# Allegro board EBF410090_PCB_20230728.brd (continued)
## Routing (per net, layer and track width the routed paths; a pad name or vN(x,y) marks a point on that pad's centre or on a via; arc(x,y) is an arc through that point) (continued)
I2C1_SCL: length 194.7
  TOP w0.156: v1(106.5,48.39) 103.81,51.08 88.04,51.08 87.3,50.34 87.3,28.75 86.84,28.3 84.18,28.3 v1(83.57,27.68) ; R164.2 127.48,68.12 J18.9 131.17,68.12 131.51,67.79 131.51,66.33 131.82,66.02 134.61,66.02 135.03,66.43 135.03,67.76 v1(134.55,68.24) ; v1(39.88,18.92) 40.36,19.4 40.36,31.72 41.26,32.62 J30.150
  ART03 w0.142: v1(39.88,18.92) 40.44,19.48 72.06,19.48 73.28,20.7 73.28,24.26 76.71,27.68 v1(83.57,27.68) ; v1(134.55,68.24) 135.7,67.08 135.7,54.13 134.53,52.96 122.99,52.96 120.6,50.57 115.44,50.57 113.26,48.39 v1(106.5,48.39)
  BOTTOM w0.156: J20.6 133.09,70.16 134.55,68.7 v1(134.55,68.24)
I2C1_SDA: length 189.1
  TOP w0.156: v1(134.55,67.24) 134.55,66.93 134.14,66.52 132.29,66.52 131.98,66.83 131.98,68.02 131.38,68.62 J18.10 127.38,68.62 R168.2 ; v1(40.89,18.92) 40.89,30.02 41.76,30.89 J30.148 ; v1(105.5,48.39) 103.37,50.52 88.37,50.52 87.78,49.94 87.78,28.35 87.12,27.68 v1(84.71,27.68)
  ART03 w0.142: v1(105.5,48.39) 106.01,48.89 113.09,48.89 115.73,51.54 120.75,51.54 122.63,53.42 134.11,53.42 135.28,54.58 135.28,66.51 v1(134.55,67.24) ; v1(84.71,27.68) 84.2,27.18 76.96,27.18 73.79,24 73.79,20.51 72.22,18.95 40.92,18.95 v1(40.89,18.92)
  BOTTOM w0.156: J20.5 132.83,69.65 134.04,68.45 134.04,67.75 v1(134.55,67.24)
I2C2_SCL_M1: length 62.8
  TOP w0.156: v1(76.58,17.02) R222.2 ; J30.55 67.01,60.78
  TOP w0.305: 67.01,60.78 v1(67.01,60.78)
  BOTTOM w0.156: v1(76.58,17.02) 77.07,16.53 81.3,16.53 82.68,17.91 82.68,47.75 81.38,49.05 81.38,52.32 80.57,53.14 73.18,53.14 67.5,58.82 67.5,60.3 v1(67.01,60.78)
I2C2_SDA_M1: length 56.9
  TOP w0.156: J30.61 65.51,60.28 v1(66.01,59.78) ; v1(81.06,17.02) R233.2
  BOTTOM w0.156: v1(66.01,59.78) 66.01,59.64 73.03,52.63 79.25,52.63 80.9,50.98 80.9,48.77 82.17,47.5 82.17,18.12 v1(81.06,17.02)
I2C3_SCL_M0: length 47.5
  TOP w0.156: J30.46 69.26,46.43 69.85,45.85 70.36,45.85 70.61,45.59 70.61,40.18 73.2,37.59 73.2,32.6 74.05,31.76 74.05,29.2 76.33,26.92 79.5,26.92 v1(79.88,26.54) ; R237.2 v1(86.49,26.03)
  ART03 w0.142: v1(79.88,26.54) 80.39,26.03 v1(86.49,26.03)
I2C3_SDA_M0: length 48.1
  TOP w0.156: v1(80.9,26.54) 80.01,27.43 76.58,27.43 74.52,29.49 74.52,31.93 73.66,32.79 73.66,37.84 71.12,40.38 71.12,48.13 69.76,49.49 J30.44 ; R238.2 v1(87.76,26.54)
  ART03 w0.142: v1(80.9,26.54) v1(87.76,26.54)
I2C4_SCL_M0: length 91.6
  TOP w0.156: J30.57 66.51,60.28 v1(67.01,59.78) ; v1(54.05,41.67) 53.47,41.08 53.47,35.18 55.5,33.15 55.5,28.07 56.26,27.3 68.58,27.3 70.1,25.78 72.26,25.78 73.28,24.76 73.28,11.3 71.86,9.89 66.79,9.89 J23.4
  BOTTOM w0.156: v1(67.01,59.78) 66.5,60.3 66.5,61.29 65.91,61.87 57.86,61.87 57.02,61.04 57.02,59.43 56.13,58.55 56.13,56.77 52.83,53.47 52.83,42.89 v1(54.05,41.67)
I2C4_SDA_M0: length 83.4
  TOP w0.156: J30.59 66.01,60.78 ; v1(54.05,42.67) 52.96,41.57 52.96,34.92 54.99,32.89 54.99,27.3 55.63,26.67 68.33,26.67 69.85,25.14 72.14,25.14 72.77,24.51 72.77,12.76 71.57,11.56 68.9,11.56 J23.5
  TOP w0.305: 66.01,60.78 v1(66.01,60.78)
  BOTTOM w0.156: v1(54.05,42.67) 53.34,43.38 53.34,53.08 56.77,56.51 56.77,58.04 58.03,59.3 58.03,60.98 58.36,61.31 65.48,61.31 v1(66.01,60.78)
I2C5_SCL_M0: length 102.8
  TOP w0.156: R166.2 127.48,46.03 J19.9 133.28,46.03 133.63,46.38 v1(133.63,52.39) ; v1(71.93,41.76) 71.63,42.06 71.63,48.26 70.26,49.62 J30.42
  ART03 w0.142: v1(71.93,41.76) 71.93,42.24 72.54,42.85 79.32,42.85 80.49,44.02 88.21,44.02 90.02,45.82 99.21,45.82 100,45.03 113.97,45.03 116.4,47.46 v1(117.83,47.46)
  ART04 w0.142: v1(117.83,47.46) 117.83,46.2 119.13,44.91 127.51,44.91 127.73,45.13 129.28,45.13 129.69,45.54 129.69,51.65 129.91,51.87 133.11,51.87 v1(133.63,52.39)
  BOTTOM w0.156: v1(133.63,52.39) 132.63,53.39 J21.6
I2C5_SDA_M0: length 96.1
  TOP w0.156: R170.2 127.38,46.53 J19.10 132.38,46.53 132.63,46.78 v1(132.63,52.39) ; v1(72.69,42.11) 72.13,42.68 72.13,48.39 70.76,49.76 J30.40
  ART03 w0.142: v1(72.69,42.11) 73.08,41.73 80.29,41.73 81.58,43.03 88.49,43.03 89.41,43.94 114.07,43.94 116.59,46.46 v1(118.83,46.46)
  ART04 w0.142: v1(118.83,46.46) 119.34,45.95 121.49,45.95 121.89,45.54 127.23,45.54 128.4,46.71 128.4,52.95 128.68,53.24 131.78,53.24 v1(132.63,52.39)
  BOTTOM w0.156: J21.5 132.13,52.89 v1(132.63,52.39)
LCD0_BL_PWM: length 204.7
  TOP w0.156: v1(83.69,12.19) 83.69,15.37 83.44,15.62 83.44,26.61 83.75,26.92 87.38,26.92 88.27,27.81 88.27,49.67 88.58,49.99 102.9,49.99 v1(104.5,48.39) ; J30.163 38.01,60.28 v1(38.51,59.78) ; v1(46.43,13.66) 46.1,14 46.1,17.25 43.41,19.94 43.41,28.6 44.2,29.39 44.2,31.57 44.76,32.14 v1(44.76,51.58) ; v1(132.55,67.24) 133.04,67.74 133.04,69.52 132.44,70.12 J18.13
  ART03 w0.142: v1(44.76,51.58) 44.22,52.12 44.22,57.68 43.38,58.52 38.73,58.52 38.51,58.74 v1(38.51,59.78) ; v1(83.69,12.19) 72.39,12.19 70.9,13.68 50.09,13.68 50.07,13.66 v1(46.43,13.66) ; v1(132.55,67.24) 134.82,64.96 134.82,54.86 133.81,53.85 122.38,53.85 120.55,52.02 115.53,52.02 112.79,49.27 105.39,49.27 v1(104.5,48.39)
LCD1_BL_PWM: length 118.3
  TOP w0.156: J30.161 38.51,60.78 v1(38.51,60.78) ; v1(124.35,49.02) 124.91,48.46 128.3,48.46 128.73,48.03 J19.13
  ART03 w0.142: v1(38.51,60.78) 38.02,60.3 38.02,58.27 38.31,57.99 43,57.99 43.71,57.28 43.71,45.06 48.64,40.13 57.68,40.13 59.92,42.37 66.55,42.37 67.69,41.22 80.82,41.22 81.53,41.93 88.8,41.93 89.92,43.05 120.65,43.05 122.15,44.55 122.15,48.74 122.43,49.02 v1(124.35,49.02)
MDIN0_PHY: length 67
  ART04 w0.113: J14.3 78.95,73.23 79.11,73.39 79.9,73.39 80.11,73.18 80.11,65.42 78,63.31 78,60.19 77.05,59.23 56.82,59.23 56.16,58.57 56.16,50.76 55.11,49.71 55.11,40.97 55.45,40.63 57.27,40.63 57.61,40.97 57.61,42.59 57.2,43 56.62,43 v1(56.31,43.3)
  BOTTOM w0.124: v1(56.31,43.3) 56.61,43 59.68,43 59.72,43.05 U16.2
MDIN1_PHY: length 76.6
  ART04 w0.113: J14.7 73.87,75.75 74.07,75.94 76.13,75.94 76.32,75.76 76.32,74.06 77.43,72.94 77.43,69.93 76.8,69.29 76.8,65 74.27,62.47 56.63,62.47 55.75,61.59 54.74,61.59 53.32,60.17 53.32,40.28 53.86,39.74 58.18,39.74 58.91,40.47 58.91,43.87 58.58,44.21 58.13,44.21 v1(57.82,44.51)
  BOTTOM w0.124: v1(57.82,44.51) 58.12,44.21 59.69,44.21 59.72,44.25 U16.5
MDIN2_PHY: length 76.1
  ART04 w0.113: J14.6 75.04,74.64 75.04,65.38 73.21,63.55 56.32,63.55 55.29,62.52 54.1,62.52 52.6,61.03 52.6,39.78 53.38,39 59.12,39 60.22,40.11 60.22,43.92 58.65,45.48 56.52,45.48 v1(56.31,45.69)
  BOTTOM w0.124: v1(56.31,45.69) 56.46,45.54 58.04,45.54 58.57,45.01 59.69,45.01 59.72,45.05 U16.7
MDIN3_PHY: length 79.5
  ART04 w0.113: J14.9 71.33,73.46 71.45,73.58 71.94,73.58 72.46,73.06 72.46,70.39 71.87,69.8 71.87,65.76 70.4,64.3 55.66,64.3 54.7,63.33 53.72,63.33 51.88,61.5 51.88,45.62 51.31,45.05 51.31,39.34 52.45,38.2 59.6,38.2 60.71,39.31 62.04,39.31 62.56,39.83 62.56,41.07 61.34,42.29 61.34,44.63 59.08,46.89 57.99,46.89 v1(57.82,47.06)
  BOTTOM w0.124: v1(57.82,47.06) 58.12,46.76 58.9,46.76 59.45,46.21 59.69,46.21 59.72,46.25 U16.10
MDIP0_PHY: length 66.9
  ART04 w0.113: J14.2 79.13,74.74 78.94,74.55 78.94,73.9 79.13,73.71 80.03,73.71 80.43,73.31 80.43,65.29 78.32,63.18 78.32,60.06 77.18,58.92 56.95,58.92 56.48,58.44 56.48,50.63 55.42,49.58 55.42,41.1 55.58,40.94 57.13,40.94 57.3,41.1 57.3,42.45 57.07,42.68 56.62,42.68 v1(56.31,42.37)
  BOTTOM w0.124: U16.1 59.72,42.65 59.7,42.67 56.61,42.67 v1(56.31,42.37)
MDIP1_PHY: length 76.5
  ART04 w0.113: v1(57.82,43.59) 58.13,43.89 58.44,43.89 58.6,43.74 58.6,40.6 58.05,40.05 53.99,40.05 53.63,40.41 53.63,60.04 54.87,61.28 55.88,61.28 56.76,62.15 74.4,62.15 77.11,64.87 77.11,69.16 77.75,69.8 77.75,73.07 76.63,74.19 76.63,75.89 76.26,76.26 74.59,76.26 74.47,76.37 74.47,76.7 74.59,76.81 76.8,76.81 77.68,75.93 J14.4
  BOTTOM w0.124: v1(57.82,43.59) 58.12,43.89 59.69,43.89 59.72,43.85 U16.4
MDIP2_PHY: length 76
  ART04 w0.113: v1(56.31,44.76) 56.31,45.06 56.42,45.17 58.52,45.17 59.91,43.78 59.91,40.24 58.99,39.32 53.51,39.32 52.92,39.91 52.92,60.89 54.23,62.2 55.42,62.2 56.45,63.23 73.34,63.23 75.35,65.24 75.35,73.31 75.6,73.55 76.18,73.55 76.41,73.33 J14.5
  BOTTOM w0.124: U16.6 59.72,44.65 59.69,44.69 58.43,44.69 57.9,45.21 56.44,45.21 56.31,45.09 v1(56.31,44.76)
MDIP3_PHY: length 79.5
  ART04 w0.113: J14.8 71.41,74.74 71.22,74.55 71.22,74.07 71.39,73.9 72.07,73.9 72.77,73.19 72.77,70.26 72.19,69.67 72.19,65.63 70.54,63.98 55.79,63.98 54.83,63.02 53.85,63.02 52.2,61.37 52.2,45.49 51.62,44.92 51.62,39.47 52.58,38.52 59.47,38.52 60.58,39.62 61.91,39.62 62.24,39.96 62.24,40.94 61.03,42.16 61.03,44.5 58.95,46.57 57.95,46.57 57.82,46.44 v1(57.82,46.13)
  BOTTOM w0.124: U16.9 59.72,45.85 59.69,45.89 59.31,45.89 58.77,46.43 58.12,46.43 v1(57.82,46.13)
MIC_INN: length 48.7
  TOP w0.124: v1(40.27,64.9) R220.1 40.27,66.64 C188.2 39.93,67.55 39.93,67.86 Z10.2 39.91,68.55 39.91,68.96 40.16,69.21 40.77,69.21 41.02,69.45 J27.1 ; J30.232 20.76,52.88 20.85,52.79 20.85,52.06 20.6,51.81 20.6,47.8 21.51,46.89 v1(21.51,46.58)
  BOTTOM w0.124: v1(40.27,64.9) 39.91,64.54 39.91,63.41 38.33,61.83 33.87,61.83 32.7,60.66 32.7,49.19 31.2,47.69 24.23,47.69 23.46,46.92 21.84,46.92 v1(21.51,46.58)
MIC_INP: length 71.4
  TOP w0.124: J27.2 38.48,69.45 38.73,69.21 39.34,69.21 39.59,68.96 39.59,68.55 Z7.2 39.6,67.83 39.6,67.58 C188.1 39.23,66.64 R216.2 v1(39.23,64.9) ; J30.230 21.26,52.88 21.18,52.79 21.18,51.92 20.92,51.67 20.92,47.94 21.28,47.58 v1(21.51,47.58)
  TOP w0.254: J26.2 47.65,82.27 J26.5 49.45,78.77 J26.3 47.65,76.77 J26.4 45.72,74.67 43.64,72.59 38.89,72.59 38.48,72.18 J27.2
  BOTTOM w0.124: v1(39.23,64.9) 39.59,64.54 39.59,63.54 38.2,62.15 33.73,62.15 32.37,60.79 32.37,49.33 31.06,48.02 24.09,48.02 23.32,47.25 21.84,47.25 v1(21.51,47.58)
MINIPCIE_3V3: length 86.3
  TOP w0.305: v1(97.18,72.77) 97.6,72.35 J24.39 97.6,70.17 v1(97.2,69.77) 96.8,70.17 J24.41
  TOP w0.381: v1(93.13,59.17) C184.1 J24.52 ; v1(102.27,59.17) C181.1 103.6,59.78 J24.24 ; v1(114.97,59.17) C183.1 115.6,59.27 J24.2
  ART03 w0.508: v1(93.13,59.17) 93.39,59.43 102.01,59.43 v1(102.27,59.17)
  BOTTOM w0.305: 109.05,49.06 103.01,49.06 102.56,48.6 C169.1 R203.1
  BOTTOM w0.508: R208.1 117.78,71.24 118.29,70.73 118.29,65.81 117.78,65.3 116.41,65.3 115.9,64.79 115.9,60.11 v1(114.97,59.17) 110.55,59.17 110.06,58.68 ; 110.06,58.68 109.57,59.17 v1(102.27,59.17) 101.65,59.79 98.86,59.79 98.15,60.5 98.15,67.16 97.2,68.1 v1(97.2,69.77) 97.29,69.86 C182.1 97.29,72.66 v1(97.18,72.77) ; 110.06,58.68 110.06,56.87
MINIPCIE_NWDISABLE: length 123.5
  TOP w0.156: v1(35.01,64.75) 35.51,64.25 J30.173 ; R211.2 v1(105.28,57.44)
  ART03 w0.142: v1(88.17,88.39) 87.66,87.88 86.72,87.88 86.28,88.31 54.41,88.31 52.83,86.74 52.83,77.98 51.87,77.01 51.87,71.55 50.16,69.85 45.09,69.85 41.66,66.42 37.08,66.42 35.42,64.75 v1(35.01,64.75)
  ART04 w0.142: v1(105.28,57.44) 104.65,58.08 104.65,71.21 102.34,73.52 102.34,83.53 101.62,84.25 88.62,84.25 86.59,86.28 86.59,88.64 86.87,88.92 87.64,88.92 v1(88.17,88.39)
MIPI0_PWR_EN: length 144.4
  TOP w0.156: v1(83.44,33.04) 85.54,35.15 85.54,49.58 84.33,50.8 79.38,50.8 78.26,51.91 J30.10
  ART03 w0.142: v1(83.44,33.04) 85.01,33.04 86.16,31.9 112.24,31.9 112.78,31.37 112.78,22.88 113.36,22.31 120.14,22.31 121.72,20.73 121.72,17.63 122.17,17.17 129.95,17.17 130.56,17.78 130.56,25.36 130.26,25.65 128.56,25.65 128.19,26.02 128.19,34.44 v1(128.45,34.7)
  BOTTOM w0.156: R172.1 119.01,52.19 119.38,51.81 126.21,51.81 127.1,50.93 127.1,36.05 v1(128.45,34.7)
MIPI1_PWR_EN: length 200
  TOP w0.156: v1(52.05,41.67) 52.05,34.43 52.96,33.53 52.96,26.8 53.85,25.91 68.2,25.91 69.6,24.51 71.75,24.51 72.26,24 v1(72.26,13.71) ; J30.47 69.01,60.28 v1(69.51,59.78) ; R171.1 122.98,48.46 v1(120.83,48.46)
  ART03 w0.142: v1(119.51,13.21) 119.01,12.71 85.34,12.71 84.84,13.21 72.77,13.21 v1(72.26,13.71)
  BOTTOM w0.156: v1(69.51,59.78) 69.51,60.03 69,60.54 69,61.94 68.58,62.36 57.15,62.36 56.01,61.21 56.01,59.31 55.5,58.8 55.5,57.02 52.32,53.85 52.32,41.94 v1(52.05,41.67) ; v1(119.51,13.21) 119.51,15.54 119.82,15.85 124.89,15.85 125.32,16.28 125.32,18.02 125.64,18.34 133.6,18.34 133.91,18.65 133.91,26.28 133.6,26.59 130.54,26.59 130.23,26.91 130.23,29.63 129.91,29.94 126.34,29.94 125.96,30.33 125.96,34.89 126.03,34.97 126.03,49.3 125.65,49.68 121.11,49.68 120.83,49.4 v1(120.83,48.46)
MIPI_CSI_RX_CLK0N: length 92.7
  TOP w0.124: v1(59.51,59.78) 60.01,60.28 J30.83
  ART03 w0.113: v1(127.78,71.65) 127.63,71.8 126.89,71.8 125.01,73.67 120.04,73.67 116.32,69.95 112.22,69.95 111.99,69.72 111.99,67.28 111.69,66.98 107.67,66.98 107.54,66.85 107.54,65.52 107.22,65.2 106.77,65.2 106.45,65.52 106.45,67.02 106.32,67.16 106.13,67.16 106,67.02 106,65.52 105.68,65.2 105.24,65.2 104.92,65.52 104.92,66.85 104.79,66.98 104.55,66.98 104.37,66.8 104.37,65.08 104.07,64.78 89.71,64.78 87.6,62.68 83.06,62.68 82.24,61.85 78.23,61.85 78.01,61.63 78.01,58.85 77.45,58.28 60.07,58.28 59.66,58.69 59.66,59.64 v1(59.51,59.78)
  BOTTOM w0.124: J20.10 128.28,72.16 v1(127.78,71.65)
MIPI_CSI_RX_CLK0P: length 92.8
  TOP w0.124: J30.85 v1(59.51,60.78)
  ART03 w0.113: v1(128.78,71.65) 128.43,71.65 127.97,72.12 127.02,72.12 125.15,73.99 119.91,73.99 116.19,70.27 112.09,70.27 111.67,69.85 111.67,67.41 111.56,67.29 107.54,67.29 107.22,66.98 107.22,65.65 107.09,65.52 106.9,65.52 106.77,65.65 106.77,67.16 106.45,67.47 106,67.47 105.69,67.16 105.69,65.65 105.55,65.52 105.37,65.52 105.23,65.65 105.23,66.98 104.92,67.29 104.42,67.29 104.05,66.93 104.05,65.21 103.94,65.1 103.7,65.1 arc(103.62,65.13) 103.59,65.21 arc(103.55,65.29) 103.47,65.33 103.25,65.33 arc(103.17,65.29) 103.13,65.21 arc(103.1,65.13) 103.02,65.1 102.8,65.1 arc(102.72,65.13) 102.68,65.21 arc(102.65,65.29) 102.57,65.33 102.35,65.33 arc(102.27,65.29) 102.23,65.21 arc(102.2,65.13) 102.12,65.1 101.9,65.1 arc(101.82,65.13) 101.78,65.21 arc(101.75,65.29) 101.67,65.33 101.44,65.33 arc(101.36,65.29) 101.33,65.21 arc(101.3,65.13) 101.22,65.1 89.58,65.1 87.47,62.99 82.93,62.99 82.1,62.16 78.1,62.16 77.7,61.76 77.7,58.98 77.32,58.6 60.2,58.6 59.97,58.82 59.97,59.97 59.51,60.44 v1(59.51,60.78)
  BOTTOM w0.124: J20.9 v1(128.78,71.65)
MIPI_CSI_RX_CLK1N: length 108.9
  TOP w0.124: J30.79 61.01,60.28 v1(60.51,59.78)
  ART03 w0.113: v1(60.51,59.78) 60.66,59.64 60.66,59.45 61.07,59.04 76.82,59.04 77.28,59.5 77.28,62.42 77.77,62.91 81.05,62.91 81.57,63.44 87.35,63.44 89.46,65.55 92.64,65.55 95.15,68.06 104.84,68.06 108.8,72.02 116.56,72.02 117.71,73.17 117.71,76.19 118.32,76.8 121.87,76.8 123.54,75.12 129.05,75.12 130.21,73.96 130.21,67.69 133.63,64.27 133.63,60.18 arc(133.6,60.08) 133.51,60.05 arc(133.41,60.01) 133.38,59.92 133.38,59.72 arc(133.41,59.63) 133.51,59.6 arc(133.6,59.56) 133.63,59.47 133.63,59.27 arc(133.6,59.18) 133.51,59.14 arc(133.41,59.11) 133.38,59.01 133.38,58.82 arc(133.41,58.73) 133.51,58.69 arc(133.6,58.65) 133.63,58.56 133.63,57.66 v1(133.33,57.35)
  BOTTOM w0.124: J21.10 131.28,55.39 131.37,55.3 133.51,55.3 133.63,55.43 133.63,57.05 v1(133.33,57.35)
MIPI_CSI_RX_CLK1P: length 108.8
  TOP w0.124: J30.81 v1(60.51,60.78)
  ART03 w0.113: v1(60.51,60.78) 60.51,60.44 60.97,59.97 60.97,59.58 61.2,59.36 76.69,59.36 76.96,59.63 76.96,62.55 77.64,63.23 80.92,63.23 81.44,63.75 87.22,63.75 89.33,65.86 92.51,65.86 95.02,68.38 104.71,68.38 108.67,72.34 116.43,72.34 117.4,73.3 117.4,76.33 118.19,77.11 122,77.11 123.67,75.44 129.18,75.44 130.53,74.09 130.53,67.82 133.95,64.4 133.95,57.66 v1(134.26,57.35)
  BOTTOM w0.124: v1(134.26,57.35) 133.96,57.05 133.96,55.29 133.64,54.98 131.37,54.98 131.28,54.89 J21.9
MIPI_CSI_RX_D0N: length 98.5
  TOP w0.124: J30.99 56.01,60.28 v1(55.51,59.78)
  ART03 w0.113: v1(127.78,72.65) 128.12,73 128.12,73.59 128.53,74 129.32,74 129.73,73.59 129.73,70.42 128.26,68.95 126.78,68.95 122.19,64.36 122.19,61.48 121.59,60.88 115.69,60.88 115.26,60.45 92.55,60.45 90.05,57.95 85.07,57.95 81.94,54.83 57.46,54.83 57.46,54.83 56.46,54.83 55.66,55.63 55.66,59.64 v1(55.51,59.78)
  BOTTOM w0.124: v1(127.78,72.65) 128.28,73.16 J20.12
MIPI_CSI_RX_D0P: length 98
  TOP w0.124: J30.101 v1(55.51,60.78)
  ART03 w0.113: v1(55.51,60.78) 55.51,60.44 55.97,59.97 55.97,55.76 56.59,55.14 57.59,55.14 57.59,55.14 65.51,55.14 arc(65.61,55.18) 65.65,55.28 arc(65.7,55.38) 65.79,55.42 65.97,55.42 arc(66.06,55.38) 66.11,55.28 arc(66.15,55.18) 66.25,55.14 66.42,55.14 arc(66.52,55.18) 66.56,55.28 arc(66.6,55.38) 66.7,55.42 66.87,55.42 arc(66.97,55.38) 67.01,55.28 arc(67.05,55.18) 67.15,55.14 67.32,55.14 arc(67.42,55.18) 67.46,55.28 arc(67.5,55.38) 67.6,55.42 67.77,55.42 arc(67.87,55.38) 67.91,55.28 arc(67.95,55.18) 68.05,55.14 68.22,55.14 arc(68.32,55.18) 68.36,55.28 arc(68.4,55.38) 68.5,55.42 68.67,55.42 arc(68.77,55.38) 68.81,55.28 arc(68.85,55.18) 68.95,55.14 69.12,55.14 arc(69.22,55.18) 69.26,55.28 arc(69.3,55.38) 69.4,55.42 69.57,55.42 arc(69.67,55.38) 69.71,55.28 arc(69.76,55.18) 69.85,55.14 70.03,55.14 arc(70.12,55.18) 70.17,55.28 arc(70.21,55.38) 70.31,55.42 70.48,55.42 arc(70.58,55.38) 70.62,55.28 arc(70.66,55.18) 70.76,55.14 70.93,55.14 arc(71.03,55.18) 71.07,55.28 arc(71.11,55.38) 71.21,55.42 71.38,55.42 arc(71.48,55.38) 71.52,55.28 arc(71.56,55.18) 71.66,55.14 71.83,55.14 arc(71.93,55.18) 71.97,55.28 arc(72.01,55.38) 72.11,55.42 72.28,55.42 arc(72.38,55.38) 72.42,55.28 arc(72.46,55.18) 72.56,55.14 72.73,55.14 arc(72.83,55.18) 72.87,55.28 arc(72.91,55.38) 73.01,55.42 73.18,55.42 arc(73.28,55.38) 73.32,55.28 arc(73.36,55.18) 73.46,55.14 81.81,55.14 84.94,58.27 89.92,58.27 92.42,60.77 115.12,60.77 115.56,61.2 121.46,61.2 121.87,61.61 121.87,64.49 126.64,69.26 128.13,69.26 129.41,70.55 129.41,73.46 129.19,73.68 128.66,73.68 128.44,73.46 128.44,73 v1(128.78,72.65)
  BOTTOM w0.124: J20.11 v1(128.78,72.65)
MIPI_CSI_RX_D1N: length 98.7
  TOP w0.124: J30.95 57.01,60.28 v1(56.51,59.78)
  ART03 w0.113: v1(56.51,59.78) 56.66,59.64 56.66,56.42 57.11,55.97 81.72,55.97 84.47,58.71 89.6,58.71 93.24,62.36 100.95,62.36 101.09,62.22 101.09,61.83 101.4,61.52 101.85,61.52 102.17,61.83 102.17,62.22 102.3,62.36 103.99,62.36 104.12,62.22 104.12,61.56 104.44,61.24 104.88,61.24 105.2,61.56 105.2,62.22 105.33,62.36 106.84,62.36 106.97,62.22 106.97,61.61 107.29,61.29 107.73,61.29 108.05,61.61 108.05,62.22 108.18,62.36 108.37,62.36 108.5,62.22 108.5,61.61 108.82,61.29 109.27,61.29 109.59,61.61 109.59,62.22 109.72,62.36 109.91,62.36 110.04,62.22 110.04,61.61 110.35,61.29 110.8,61.29 111.12,61.61 111.12,62.22 111.25,62.36 111.44,62.36 111.57,62.22 111.57,61.61 111.89,61.29 112.34,61.29 112.65,61.61 112.65,62.22 112.79,62.36 112.97,62.36 113.11,62.22 113.11,61.61 113.42,61.29 113.87,61.29 114.19,61.61 114.19,62.22 114.32,62.36 118.43,62.36 122.31,66.24 122.31,68.4 122.99,69.08 123.84,69.08 125.6,70.84 127.59,70.84 v1(127.78,70.65)
  BOTTOM w0.124: v1(127.78,70.65) 128.28,71.16 J20.8
MIPI_CSI_RX_D1P: length 98.9
  TOP w0.124: J30.97 v1(56.51,60.78)
  ART03 w0.113: v1(128.78,70.65) 128.45,70.65 127.95,71.16 125.47,71.16 123.71,69.39 122.86,69.39 122,68.53 122,66.37 118.3,62.67 114.19,62.67 113.87,62.35 113.87,61.74 113.74,61.61 113.55,61.61 113.42,61.74 113.42,62.35 113.1,62.67 112.66,62.67 112.34,62.35 112.34,61.74 112.21,61.61 112.02,61.61 111.89,61.74 111.89,62.35 111.57,62.67 111.12,62.67 110.8,62.35 110.8,61.74 110.67,61.61 110.49,61.61 110.35,61.74 110.35,62.35 110.04,62.67 109.59,62.67 109.27,62.35 109.27,61.74 109.14,61.61 108.95,61.61 108.82,61.74 108.82,62.35 108.5,62.67 108.05,62.67 107.74,62.35 107.74,61.74 107.6,61.61 107.42,61.61 107.28,61.74 107.28,62.35 106.97,62.67 105.2,62.67 104.89,62.35 104.89,61.69 104.75,61.55 104.57,61.55 104.43,61.69 104.43,62.35 104.12,62.67 102.17,62.67 101.85,62.35 101.85,61.97 101.72,61.83 101.53,61.83 101.4,61.97 101.4,62.35 101.08,62.67 93.11,62.67 89.47,59.03 84.34,59.03 81.59,56.28 57.25,56.28 56.97,56.55 56.97,56.82 arc(57.01,56.9) 57.1,56.94 arc(57.19,56.98) 57.23,57.07 57.23,57.27 arc(57.19,57.36) 57.1,57.39 arc(57.01,57.43) 56.97,57.52 56.97,57.72 arc(57.01,57.81) 57.1,57.84 arc(57.19,57.88) 57.23,57.97 57.23,58.17 arc(57.19,58.26) 57.1,58.29 arc(57.01,58.33) 56.97,58.42 56.97,58.62 arc(57.01,58.71) 57.1,58.75 arc(57.19,58.78) 57.23,58.87 57.23,59.07 arc(57.19,59.16) 57.1,59.2 arc(57.01,59.23) 56.97,59.32 56.97,59.97 56.51,60.44 v1(56.51,60.78)
  BOTTOM w0.124: J20.7 v1(128.78,70.65)
MIPI_CSI_RX_D2N: length 88.9
  TOP w0.124: v1(57.51,59.78) 58.01,60.28 J30.91
  ART03 w0.113: v1(123.06,72) 123.29,72.23 123.29,72.76 123.71,73.18 124.74,73.18 125.16,72.76 125.16,71.52 123.51,69.87 120.94,69.87 119.02,67.95 119.02,64.34 117.97,63.28 117.3,63.28 116.98,63.6 116.98,65.06 116.85,65.19 116.66,65.19 116.53,65.06 116.53,63.6 116.21,63.28 91.15,63.28 87.36,59.5 81,59.5 78.26,56.76 58.07,56.76 57.66,57.17 57.66,59.64 v1(57.51,59.78)
MIPI_CSI_RX_D2P: length 87.6
  TOP w0.124: J30.93 v1(57.51,60.78)
  ART03 w0.113: v1(57.51,60.78) 57.51,60.44 57.97,59.97 57.97,59.29 arc(58.01,59.2) 58.11,59.16 arc(58.2,59.12) 58.24,59.03 58.24,58.84 arc(58.2,58.75) 58.11,58.71 arc(58.01,58.67) 57.97,58.58 57.97,58.39 arc(58.01,58.3) 58.11,58.26 arc(58.2,58.22) 58.24,58.12 58.24,57.94 arc(58.2,57.85) 58.11,57.81 arc(58.01,57.77) 57.97,57.67 57.97,57.3 58.2,57.07 78.13,57.07 80.87,59.82 87.23,59.82 91.02,63.6 116.08,63.6 116.21,63.73 116.21,65.19 116.53,65.51 116.98,65.51 117.3,65.19 117.3,63.73 117.43,63.6 117.84,63.6 118.71,64.47 118.71,68.09 120.81,70.19 123.38,70.19 124.84,71.65 124.84,72.63 124.61,72.86 123.84,72.86 123.61,72.63 123.61,72.12 123.72,72 v1(124.08,72)
MIPI_CSI_RX_D3N: length 85.5
  TOP w0.124: J30.87 59.01,60.28 v1(58.51,59.78)
  ART03 w0.113: v1(58.51,59.78) 58.66,59.64 58.66,57.95 59.07,57.54 77.89,57.54 81.33,60.98 82.46,60.98 arc(82.56,60.94) 82.6,60.84 arc(82.64,60.75) 82.74,60.7 82.91,60.7 arc(83.01,60.75) 83.05,60.84 arc(83.09,60.94) 83.19,60.98 83.36,60.98 arc(83.46,60.94) 83.5,60.84 arc(83.55,60.75) 83.64,60.7 83.82,60.7 arc(83.91,60.75) 83.96,60.84 arc(84,60.94) 84.1,60.98 84.35,60.98 85.28,61.91 87.87,61.91 88.62,62.66 arc(88.7,62.7) 88.79,62.66 arc(88.87,62.63) 88.95,62.66 89.11,62.82 arc(89.14,62.9) 89.11,62.98 arc(89.07,63.06) 89.11,63.15 89.26,63.3 arc(89.34,63.33) 89.42,63.3 arc(89.51,63.27) 89.59,63.3 89.74,63.45 arc(89.78,63.54) 89.74,63.62 arc(89.71,63.7) 89.74,63.78 89.96,64 111.57,64 111.89,64.31 111.89,65.72 112.02,65.85 112.2,65.85 112.34,65.72 112.34,64.31 112.65,64 113.1,64 113.42,64.31 113.42,65.79 113.53,65.9 113.76,65.9 113.87,65.79 113.87,64.31 114.19,64 114.72,64 115.11,64.39 115.11,68.35 115.23,68.47 118.07,68.47 119.94,70.33 119.94,72.12 120.47,72.65 121.27,72.65 121.38,72.54 121.38,72.37 R185.1 v1(121.03,72)
MIPI_CSI_RX_D3P: length 84.2
  TOP w0.124: J30.89 v1(58.51,60.78)
  ART03 w0.113: v1(122.05,72.02) 121.7,72.37 121.7,72.67 121.4,72.97 120.34,72.97 119.62,72.25 119.62,70.46 117.94,68.78 115.09,68.78 114.8,68.48 114.8,64.52 114.59,64.31 114.32,64.31 114.19,64.44 114.19,65.92 113.89,66.22 113.4,66.22 113.1,65.92 113.1,64.44 112.97,64.31 112.78,64.31 112.65,64.44 112.65,65.85 112.34,66.17 111.89,66.17 111.57,65.85 111.57,64.44 111.44,64.31 89.82,64.31 87.74,62.23 85.15,62.23 84.22,61.3 81.2,61.3 77.76,57.86 59.2,57.86 58.97,58.09 58.97,59.97 58.51,60.44 v1(58.51,60.78)
MIPI_DSI_TX0_CLKN: length 122.2
  TOP w0.124: J18.24 130.82,75.62 130.91,75.54 132.39,75.54 v1(132.69,75.84) ; J30.121 v1(50.51,63.75)
  ART03 w0.113: v1(132.69,75.84) 132.69,75.49 132.58,75.38 131.67,75.38 129.43,77.62 127.91,77.62 124.8,80.73 121.87,80.73 120.95,79.82 117.71,79.82 117.57,79.95 117.57,81.5 117.26,81.81 116.81,81.81 116.49,81.5 116.49,79.95 116.36,79.82 116.17,79.82 116.04,79.95 116.04,81.5 115.72,81.81 115.27,81.81 114.96,81.5 114.96,79.95 114.83,79.82 114.64,79.82 114.51,79.95 114.51,81.5 114.19,81.81 113.74,81.81 113.42,81.5 113.42,79.95 113.29,79.82 113,79.82 112.86,79.95 112.86,81.06 112.55,81.38 112.1,81.38 111.78,81.06 111.78,79.95 111.65,79.82 111.46,79.82 111.33,79.95 111.33,81.06 111.01,81.38 110.56,81.38 110.25,81.06 110.25,79.95 110.12,79.82 109.93,79.82 109.8,79.95 109.8,81.06 109.48,81.38 109.03,81.38 108.71,81.06 108.71,79.95 108.58,79.82 108.11,79.82 107.71,79.42 107.71,74.06 107.54,73.89 arc(107.45,73.85) 107.35,73.89 arc(107.26,73.93) 107.16,73.89 107.03,73.76 arc(107,73.66) 107.03,73.57 arc(107.07,73.47) 107.03,73.38 106.91,73.25 arc(106.81,73.21) 106.72,73.25 arc(106.62,73.29) 106.53,73.25 106.4,73.12 arc(106.36,73.03) 106.4,72.93 arc(106.44,72.84) 106.4,72.74 106.27,72.61 arc(106.17,72.57) 106.08,72.61 arc(105.98,72.65) 105.89,72.61 105.76,72.48 arc(105.72,72.39) 105.76,72.29 arc(105.8,72.2) 105.76,72.1 105.63,71.97 arc(105.54,71.93) 105.44,71.97 arc(105.34,72.01) 105.25,71.97 105.12,71.85 arc(105.08,71.75) 105.12,71.66 arc(105.16,71.56) 105.12,71.46 104.99,71.34 arc(104.9,71.3) 104.8,71.34 arc(104.71,71.38) 104.61,71.34 104.48,71.21 arc(104.44,71.11) 104.48,71.02 arc(104.52,70.92) 104.48,70.83 104.22,70.56 91.39,70.56 86.31,65.48 76.49,65.48 73.31,62.3 53.7,62.3 arc(53.59,62.35) 53.54,62.46 arc(53.5,62.56) 53.39,62.61 53.25,62.61 arc(53.14,62.56) 53.09,62.46 arc(53.05,62.35) 52.94,62.3 52.7,62.3 arc(52.6,62.34) 52.56,62.44 arc(52.51,62.54) 52.41,62.58 52.25,62.58 arc(52.15,62.54) 52.1,62.44 arc(52.06,62.34) 51.96,62.3 51.8,62.3 arc(51.7,62.34) 51.65,62.44 arc(51.61,62.54) 51.51,62.58 51.34,62.58 arc(51.24,62.54) 51.2,62.44 arc(51.16,62.34) 51.06,62.3 50.82,62.3 50.28,62.84 50.28,63.64 50.39,63.75 v1(50.51,63.75)
MIPI_DSI_TX0_CLKP: length 122.1
  TOP w0.124: v1(50.51,64.75) 50.01,64.25 J30.123 ; J18.23 130.82,75.12 130.91,75.21 132.39,75.21 v1(132.69,74.91)
  ART03 w0.113: v1(50.51,64.75) 50.51,64.43 49.96,63.88 49.96,62.71 50.69,61.98 73.44,61.98 76.62,65.16 86.44,65.16 91.52,70.24 104.35,70.24 108.03,73.93 108.03,79.29 108.24,79.5 108.71,79.5 109.03,79.82 109.03,80.93 109.16,81.06 109.35,81.06 109.48,80.93 109.48,79.82 109.8,79.5 110.25,79.5 110.56,79.82 110.56,80.93 110.7,81.06 110.88,81.06 111.01,80.93 111.01,79.82 111.33,79.5 111.78,79.5 112.1,79.82 112.1,80.93 112.23,81.06 112.42,81.06 112.55,80.93 112.55,79.82 112.87,79.5 113.42,79.5 113.74,79.82 113.74,81.36 113.87,81.5 114.06,81.5 114.19,81.36 114.19,79.82 114.51,79.5 114.96,79.5 115.27,79.82 115.27,81.36 115.41,81.5 115.59,81.5 115.72,81.36 115.72,79.82 116.04,79.5 116.49,79.5 116.81,79.82 116.81,81.36 116.94,81.5 117.13,81.5 117.26,81.36 117.26,79.82 117.58,79.5 121.08,79.5 122,80.42 124.67,80.42 127.78,77.31 129.3,77.31 131.54,75.06 132.54,75.06 v1(132.69,74.91)
MIPI_DSI_TX0_D0N: length 125.4
  TOP w0.124: J30.117 v1(51.51,63.75) ; J18.27 130.82,77.12 130.91,77.04 135,77.04 135.74,76.3 135.74,71.25 135.28,70.79 135.28,70.38 v1(135.55,70.11)
  ART03 w0.113: v1(51.51,63.75) 51.51,64.08 51.97,64.55 51.97,64.68 51.98,64.68 51.98,64.94 51.84,65.08 51.84,65.32 51.42,65.73 49.4,65.73 48.55,64.88 48.55,62.42 49.7,61.27 73.9,61.27 76.9,64.28 87.08,64.28 91.7,68.9 104.55,68.9 109.78,74.13 114.19,74.13 115.02,74.97 115.02,76.35 115.65,76.98 117,76.98 118.05,78.03 121.23,78.03 122.78,79.58 123.93,79.58 127.14,76.37 129.1,76.37 130.95,74.52 130.95,70.95 133.03,68.87 134.85,68.87 135.43,69.46 135.43,69.99 v1(135.55,70.11)
MIPI_DSI_TX0_D0P: length 125.4
  TOP w0.124: v1(51.51,64.75) 51.01,64.25 J30.119 ; v1(134.65,70.11) 134.95,70.41 134.95,70.92 135.41,71.39 135.41,76.16 134.87,76.71 130.91,76.71 130.82,76.62 J18.26
  ART03 w0.113: v1(134.65,70.11) 134.95,70.11 135.12,69.94 135.12,69.59 134.72,69.19 133.16,69.19 132.99,69.36 arc(132.96,69.44) 132.99,69.53 arc(133.03,69.61) 132.99,69.7 132.84,69.85 arc(132.76,69.88) 132.67,69.85 132.67,69.85 arc(132.59,69.81) 132.5,69.85 132.35,70 arc(132.32,70.08) 132.35,70.17 132.35,70.17 arc(132.39,70.25) 132.35,70.34 132.2,70.49 arc(132.12,70.52) 132.04,70.49 132.03,70.49 arc(131.95,70.45) 131.87,70.49 131.27,71.08 131.27,74.65 129.24,76.68 127.27,76.68 124.06,79.89 122.65,79.89 121.1,78.34 117.92,78.34 116.87,77.29 115.52,77.29 114.71,76.48 114.71,75.1 114.06,74.45 109.65,74.45 109.39,74.19 arc(109.3,74.15) 109.2,74.19 arc(109.11,74.23) 109.01,74.19 108.88,74.06 arc(108.84,73.96) 108.88,73.87 arc(108.92,73.77) 108.88,73.68 108.75,73.55 arc(108.66,73.51) 108.56,73.55 arc(108.47,73.59) 108.37,73.55 108.25,73.42 arc(108.21,73.33) 108.25,73.23 arc(108.28,73.13) 108.25,73.04 108.12,72.91 arc(108.02,72.87) 107.93,72.91 arc(107.83,72.95) 107.74,72.91 107.61,72.78 arc(107.57,72.69) 107.61,72.59 arc(107.65,72.5) 107.61,72.4 107.48,72.27 arc(107.38,72.23) 107.29,72.27 arc(107.19,72.31) 107.1,72.27 106.97,72.14 arc(106.93,72.05) 106.97,71.95 arc(107.01,71.86) 106.97,71.76 106.84,71.64 arc(106.75,71.6) 106.65,71.64 arc(106.55,71.67) 106.46,71.64 106.33,71.51 arc(106.29,71.41) 106.33,71.32 arc(106.37,71.22) 106.33,71.13 106.2,71 arc(106.11,70.96) 106.01,71 arc(105.92,71.04) 105.82,71 105.69,70.87 arc(105.65,70.77) 105.69,70.68 arc(105.73,70.58) 105.69,70.49 104.42,69.21 91.57,69.21 86.94,64.59 76.77,64.59 73.76,61.59 49.83,61.59 48.87,62.55 48.87,64.75 49.53,65.42 51.29,65.42 51.51,65.2 v1(51.51,64.75)
MIPI_DSI_TX0_D1N: length 125.3
  TOP w0.124: v1(134.44,74.31) 134.17,74.04 130.91,74.04 130.82,74.12 J18.21 ; J30.113 v1(52.51,63.75)
  ART03 w0.113: v1(52.51,63.75) 52.51,64.02 52.98,64.49 52.98,65.45 53.17,65.63 55.68,65.63 57.16,64.15 67.65,64.15 70.88,67.37 84.59,67.37 90.67,73.46 101.9,73.46 102.4,73.95 102.4,78.41 arc(102.42,78.47) 102.48,78.49 arc(102.54,78.52) 102.57,78.58 102.57,78.86 arc(102.54,78.92) 102.48,78.94 arc(102.42,78.97) 102.4,79.03 102.4,79.27 arc(102.43,79.34) 102.51,79.37 arc(102.58,79.41) 102.61,79.48 102.61,79.72 arc(102.58,79.79) 102.51,79.83 arc(102.43,79.86) 102.4,79.93 102.4,80.17 arc(102.43,80.25) 102.51,80.28 arc(102.58,80.31) 102.61,80.38 102.61,80.62 arc(102.58,80.7) 102.51,80.73 arc(102.43,80.76) 102.4,80.84 102.4,81.07 arc(102.43,81.15) 102.51,81.18 arc(102.58,81.21) 102.61,81.29 102.61,81.52 arc(102.58,81.6) 102.51,81.63 arc(102.43,81.66) 102.4,81.74 102.4,81.97 arc(102.43,82.05) 102.51,82.08 arc(102.58,82.11) 102.61,82.19 102.61,82.42 arc(102.58,82.5) 102.51,82.53 arc(102.43,82.56) 102.4,82.64 102.4,82.88 arc(102.43,82.95) 102.51,82.98 arc(102.58,83.01) 102.61,83.09 102.61,83.33 arc(102.58,83.4) 102.51,83.43 arc(102.43,83.47) 102.4,83.54 102.4,83.78 arc(102.43,83.85) 102.51,83.89 arc(102.58,83.92) 102.61,83.99 102.61,84.23 arc(102.58,84.31) 102.51,84.34 arc(102.43,84.37) 102.4,84.44 102.4,84.68 arc(102.43,84.76) 102.51,84.79 arc(102.58,84.82) 102.61,84.9 102.61,85.13 arc(102.58,85.21) 102.51,85.24 arc(102.43,85.27) 102.4,85.35 102.4,85.63 102.64,85.88 120.46,85.88 121.17,86.59 122.45,86.59 122.58,86.46 122.58,86.07 122.9,85.75 123.34,85.75 123.66,86.07 123.66,86.46 123.79,86.59 123.98,86.59 124.11,86.46 124.11,86.07 124.43,85.75 124.88,85.75 125.2,86.07 125.2,86.46 125.33,86.59 125.51,86.59 125.65,86.46 125.65,86.07 125.96,85.75 126.41,85.75 126.73,86.07 126.73,86.46 126.86,86.59 127.05,86.59 127.18,86.46 127.18,86.07 127.5,85.75 127.95,85.75 128.26,86.07 128.26,86.46 128.4,86.59 128.64,86.59 128.77,86.46 128.77,83.64 130.9,81.51 134.94,81.51 135.17,81.28 135.17,74.22 134.98,74.03 134.72,74.03 v1(134.44,74.31)
MIPI_DSI_TX0_D1P: length 125.1
  TOP w0.124: J30.115 52.01,64.25 v1(52.51,64.75) ; J18.20 130.82,73.62 130.91,73.71 134.12,73.71 v1(134.44,73.38)
  ART03 w0.113: v1(52.51,64.75) 52.56,64.75 52.67,64.87 52.67,65.58 53.04,65.95 55.81,65.95 57.29,64.46 67.52,64.46 70.75,67.69 84.45,67.69 90.54,73.77 101.77,73.77 102.08,74.08 102.08,85.76 102.51,86.19 120.33,86.19 121.04,86.9 122.58,86.9 122.89,86.59 122.89,86.2 123.03,86.07 123.21,86.07 123.35,86.2 123.35,86.59 123.66,86.9 124.11,86.9 124.43,86.59 124.43,86.2 124.56,86.07 124.75,86.07 124.88,86.2 124.88,86.59 125.2,86.9 125.65,86.9 125.96,86.59 125.96,86.2 126.09,86.07 126.28,86.07 126.41,86.2 126.41,86.59 126.73,86.9 127.18,86.9 127.5,86.59 127.5,86.2 127.63,86.07 127.82,86.07 127.95,86.2 127.95,86.59 128.26,86.9 128.77,86.9 129.08,86.59 129.08,83.77 131.03,81.82 135.07,81.82 135.48,81.41 135.48,74.09 135.11,73.72 134.77,73.72 v1(134.44,73.38)
MIPI_DSI_TX0_D2N: length 125.5
  TOP w0.124: J30.109 v1(53.51,63.75) ; J18.18 130.59,72.62 130.68,72.54 132.59,72.54 v1(132.89,72.84)
  ART03 w0.113: v1(132.89,72.84) 133.2,72.53 133.35,72.53 133.58,72.76 133.58,76.62 133.42,76.77 131.19,76.77 129.84,78.12 128.31,78.12 126.52,79.91 126.52,83.27 126.31,83.48 123.6,83.48 123.47,83.35 123.47,81.57 123.15,81.25 122.71,81.25 122.39,81.57 122.39,83.35 122.26,83.48 121.23,83.48 121.1,83.35 121.1,82.92 120.78,82.6 120.34,82.6 120.02,82.92 120.02,83.35 119.89,83.48 119.7,83.48 119.57,83.35 119.57,82.92 119.25,82.6 118.8,82.6 118.48,82.92 118.48,83.35 118.35,83.48 118.17,83.48 118.03,83.35 118.03,82.59 117.69,82.24 117.25,82.24 116.95,82.54 116.95,83.35 116.82,83.48 116.63,83.48 116.5,83.35 116.5,82.57 116.2,82.27 115.76,82.27 115.42,82.61 115.42,83.4 115.28,83.53 115.04,83.53 114.91,83.4 114.91,82.59 114.6,82.27 114.15,82.27 113.83,82.59 113.83,83.35 113.7,83.48 113.46,83.48 arc(113.34,83.43) 113.3,83.32 arc(113.25,83.21) 113.14,83.16 113.01,83.16 arc(112.89,83.21) 112.85,83.32 arc(112.8,83.43) 112.69,83.48 112.56,83.48 arc(112.44,83.43) 112.4,83.32 arc(112.35,83.21) 112.24,83.16 112.1,83.16 arc(111.99,83.21) 111.94,83.32 arc(111.9,83.43) 111.78,83.48 111.65,83.48 arc(111.54,83.43) 111.49,83.32 arc(111.45,83.21) 111.33,83.16 111.2,83.16 arc(111.09,83.21) 111.04,83.32 arc(111,83.43) 110.88,83.48 110.75,83.48 arc(110.64,83.43) 110.59,83.32 arc(110.54,83.21) 110.43,83.16 110.3,83.16 arc(110.19,83.21) 110.14,83.32 arc(110.09,83.43) 109.98,83.48 109.85,83.48 arc(109.74,83.43) 109.69,83.32 arc(109.64,83.21) 109.53,83.16 109.4,83.16 arc(109.28,83.21) 109.24,83.32 arc(109.19,83.43) 109.08,83.48 108.95,83.48 arc(108.83,83.43) 108.79,83.32 arc(108.74,83.21) 108.63,83.16 108.5,83.16 arc(108.38,83.21) 108.34,83.32 arc(108.29,83.43) 108.18,83.48 108.04,83.48 arc(107.93,83.43) 107.88,83.32 arc(107.84,83.21) 107.72,83.16 107.59,83.16 arc(107.48,83.21) 107.43,83.32 arc(107.39,83.43) 107.27,83.48 107.14,83.48 arc(107.03,83.43) 106.98,83.32 arc(106.94,83.21) 106.82,83.16 106.69,83.16 arc(106.58,83.21) 106.53,83.32 arc(106.48,83.43) 106.37,83.48 106.24,83.48 arc(106.13,83.43) 106.08,83.32 arc(106.03,83.21) 105.92,83.16 105.79,83.16 arc(105.68,83.21) 105.63,83.32 arc(105.58,83.43) 105.47,83.48 104.63,83.48 104.29,83.14 104.29,71.81 103.63,71.14 91.05,71.14 85.83,65.93 76.09,65.93 72.86,62.7 54.24,62.7 53.51,63.43 v1(53.51,63.75)
MIPI_DSI_TX0_D2P: length 125.1
  TOP w0.124: J30.111 53.01,64.25 v1(53.51,64.75) ; v1(132.89,71.91) 132.59,72.21 130.91,72.21 130.82,72.12 J18.17
  ART03 w0.113: v1(53.51,64.75) 53.51,64.41 53.97,63.95 53.97,63.41 54.37,63.01 72.73,63.01 75.96,66.24 85.7,66.24 90.92,71.46 103.5,71.46 103.98,71.94 103.98,83.27 104.5,83.79 113.83,83.79 114.15,83.48 114.15,82.72 114.28,82.59 114.46,82.59 114.6,82.72 114.6,83.53 114.91,83.84 115.42,83.84 115.73,83.53 115.73,82.74 115.89,82.59 116.07,82.59 116.18,82.7 116.18,83.48 116.5,83.79 116.95,83.79 117.27,83.48 117.27,82.67 117.38,82.56 117.56,82.56 117.72,82.72 117.72,83.48 118.03,83.79 118.48,83.79 118.8,83.48 118.8,83.05 118.93,82.92 119.12,82.92 119.25,83.05 119.25,83.48 119.57,83.79 120.02,83.79 120.33,83.48 120.33,83.05 120.47,82.92 120.65,82.92 120.79,83.05 120.79,83.48 121.1,83.79 122.39,83.79 122.7,83.48 122.7,81.7 122.84,81.57 123.02,81.57 123.16,81.7 123.16,83.48 123.47,83.79 126.44,83.79 126.83,83.4 126.83,80.04 128.44,78.43 129.97,78.43 131.32,77.09 133.55,77.09 133.89,76.75 133.89,72.63 133.48,72.22 133.2,72.22 v1(132.89,71.91)
MIPI_DSI_TX0_D3N: length 125.1
  TOP w0.124: J30.105 v1(54.51,63.75) ; J18.30 130.82,78.62 130.91,78.54 132.44,78.54 v1(132.74,78.84)
  ART03 w0.113: v1(54.51,63.75) 54.51,64.01 54.62,64.12 55.42,64.12 56.13,63.41 69.29,63.41 69.6,63.73 69.6,64.63 69.74,64.76 69.92,64.76 70.05,64.63 70.05,63.73 70.37,63.41 70.87,63.41 71.17,63.71 71.17,66.5 71.33,66.66 71.57,66.66 71.71,66.53 71.71,64.12 72.02,63.8 72.47,63.8 72.79,64.12 72.79,66.53 72.92,66.66 73.16,66.66 73.29,66.53 73.29,65.72 73.61,65.4 74.06,65.4 74.38,65.72 74.38,66.53 74.51,66.66 85.24,66.66 90.57,71.98 102.74,71.98 103.33,72.57 103.33,85.02 103.47,85.17 113.26,85.17 113.56,84.86 122.72,84.86 arc(122.79,84.83) 122.82,84.76 arc(122.85,84.69) 122.93,84.66 123.17,84.66 arc(123.25,84.69) 123.28,84.76 arc(123.31,84.83) 123.38,84.86 123.63,84.86 arc(123.7,84.83) 123.73,84.76 arc(123.76,84.69) 123.83,84.66 124.08,84.66 arc(124.15,84.69) 124.18,84.76 arc(124.21,84.83) 124.28,84.86 124.53,84.86 arc(124.6,84.83) 124.63,84.76 arc(124.66,84.69) 124.73,84.66 124.98,84.66 arc(125.05,84.69) 125.08,84.76 arc(125.11,84.83) 125.18,84.86 125.43,84.86 arc(125.5,84.83) 125.53,84.76 arc(125.56,84.69) 125.63,84.66 125.88,84.66 arc(125.95,84.69) 125.98,84.76 arc(126.01,84.83) 126.08,84.86 126.33,84.86 arc(126.4,84.83) 126.43,84.76 arc(126.47,84.67) 126.56,84.63 126.76,84.63 arc(126.85,84.67) 126.88,84.76 arc(126.91,84.83) 126.99,84.86 127.24,84.86 127.45,84.65 127.45,81.17 127.82,80.8 129.24,80.8 129.46,80.57 129.46,79.68 129.87,79.27 131.71,79.27 132.22,79.78 132.22,80.53 132.35,80.66 132.54,80.66 132.67,80.53 132.67,79.78 132.99,79.46 133.49,79.46 133.81,79.78 133.81,80.5 133.96,80.66 134.17,80.66 134.33,80.5 134.33,78.69 134.04,78.4 132.9,78.4 132.74,78.56 v1(132.74,78.84)
MIPI_DSI_TX0_D3P: length 125.7
  TOP w0.124: J18.29 130.82,78.12 130.91,78.21 132.44,78.21 v1(132.74,77.91) ; v1(54.51,64.75) 54.01,64.25 J30.107
  ART03 w0.113: v1(132.74,77.91) 132.92,78.09 134.17,78.09 134.65,78.56 134.65,80.63 134.31,80.97 133.83,80.97 133.49,80.63 133.49,79.91 133.36,79.78 133.12,79.78 132.99,79.91 132.99,80.66 132.67,80.97 132.22,80.97 131.91,80.66 131.91,79.91 131.58,79.59 130.01,79.59 129.78,79.81 129.78,80.7 129.37,81.11 127.95,81.11 127.76,81.3 127.76,84.78 127.37,85.18 113.69,85.18 113.39,85.48 103.34,85.48 103.01,85.15 103.01,72.7 102.61,72.3 90.44,72.3 85.11,66.98 74.38,66.98 74.06,66.66 74.06,65.85 73.93,65.72 73.74,65.72 73.61,65.85 73.61,66.66 73.29,66.98 72.79,66.98 72.47,66.66 72.47,64.25 72.34,64.12 72.15,64.12 72.02,64.25 72.02,66.66 71.71,66.98 71.2,66.98 70.85,66.63 70.85,63.84 70.74,63.73 70.5,63.73 70.37,63.86 70.37,64.76 70.05,65.07 69.6,65.07 69.29,64.76 69.29,63.86 69.16,63.73 56.26,63.73 55.55,64.44 54.83,64.44 v1(54.51,64.75)
MIPI_DSI_TX1_CLKN: length 91
  TOP w0.124: v1(115.81,53.74) 116.11,53.44 129.06,53.44 129.14,53.53 J19.24
  TOP w0.156: v1(50.26,51.58) 50.76,52.08 J30.120
  ART03 w0.113: v1(50.26,51.58) 50.12,51.72 49.29,51.72 49.17,51.61 49.17,49.21 49.44,48.94 49.98,48.94 50.24,49.21 50.24,49.58 50.6,49.94 59.92,49.94 61.7,48.16 66.71,48.16 69.67,51.11 84.81,51.11 86.14,52.45 104.3,52.45 105.37,53.52 115.58,53.52 v1(115.81,53.74)
MIPI_DSI_TX1_CLKP: length 91.5
  TOP w0.124: J19.23 129.14,53.03 129.06,53.11 116.11,53.11 v1(115.81,52.81)
  TOP w0.156: J30.122 v1(50.26,52.58)
  ART03 w0.113: v1(115.81,52.81) 115.81,53.09 115.69,53.2 105.5,53.2 104.43,52.13 86.27,52.13 84.94,50.8 69.8,50.8 66.84,47.84 61.57,47.84 59.79,49.62 50.73,49.62 50.56,49.45 50.56,49.08 50.11,48.63 49.31,48.63 48.86,49.08 48.86,51.74 49.16,52.04 50.11,52.04 50.26,52.19 v1(50.26,52.58)
MIPI_DSI_TX1_D0N: length 94.2
  TOP w0.124: J19.27 129.14,55.03 129.06,54.94 114.14,54.94 v1(113.89,55.19)
  TOP w0.156: J30.116 51.76,52.08 v1(51.26,51.58)
  ART03 w0.113: v1(113.89,55.19) 113.64,54.93 104.02,54.93 103.7,54.62 103.7,53.84 103.57,53.71 103.38,53.71 103.25,53.84 103.25,54.62 102.93,54.93 102.49,54.93 102.17,54.62 102.17,53.84 102.04,53.71 101.85,53.71 101.72,53.84 101.72,54.62 101.4,54.93 100.95,54.93 100.63,54.62 100.63,53.84 100.5,53.71 100.32,53.71 100.18,53.84 100.18,54.62 99.87,54.93 99.42,54.93 99.1,54.62 99.1,53.84 98.97,53.71 98.78,53.71 98.65,53.84 98.65,54.62 98.33,54.93 89.24,54.93 88.09,56.08 85.17,56.08 82.47,53.39 56.18,53.39 55.68,52.88 55.68,51.15 55.44,50.91 52.4,50.91 arc(52.27,50.97) 52.22,51.1 arc(52.16,51.23) 52.03,51.28 51.95,51.28 arc(51.82,51.23) 51.76,51.1 arc(51.71,50.97) 51.58,50.91 51.28,50.91 51.09,51.1 51.09,51.41 v1(51.26,51.58)
MIPI_DSI_TX1_D0P: length 94.3
  TOP w0.124: J19.26 129.14,54.53 129.06,54.61 114.24,54.61 v1(113.89,54.26)
  TOP w0.156: J30.118 v1(51.26,52.58)
  ART03 w0.113: v1(51.26,52.58) 51.26,52.24 50.77,51.75 50.77,50.97 51.15,50.6 55.57,50.6 55.99,51.02 55.99,52.75 56.32,53.07 82.6,53.07 85.3,55.77 87.96,55.77 89.11,54.62 98.2,54.62 98.33,54.49 98.33,53.71 98.65,53.39 99.1,53.39 99.42,53.71 99.42,54.49 99.55,54.62 99.74,54.62 99.87,54.49 99.87,53.71 100.18,53.39 100.63,53.39 100.95,53.71 100.95,54.49 101.08,54.62 101.27,54.62 101.4,54.49 101.4,53.71 101.72,53.39 102.17,53.39 102.48,53.71 102.48,54.49 102.62,54.62 102.8,54.62 102.94,54.49 102.94,53.71 103.25,53.39 103.7,53.39 104.02,53.71 104.02,54.49 104.15,54.62 113.54,54.62 v1(113.89,54.26)
MIPI_DSI_TX1_D1N: length 94.3
  TOP w0.124: v1(51.38,47.83) 51.68,47.54 52.18,47.54 52.35,47.7 52.35,52.79 52.26,52.88 J30.114 ; v1(113.87,52.21) 114.14,51.94 129.06,51.94 129.14,52.03 J19.21
  ART03 w0.113: v1(51.38,47.83) 51.38,47.5 51.5,47.39 51.99,47.39 52.25,47.65 52.25,48.76 52.66,49.17 59.43,49.17 61.16,47.44 67.01,47.44 69.86,50.29 86.65,50.29 87.51,51.15 105.08,51.15 105.21,51.28 105.21,51.79 105.53,52.11 105.98,52.11 106.29,51.79 106.29,51.28 106.43,51.15 106.61,51.15 106.74,51.28 106.74,51.87 107.09,52.21 107.53,52.21 107.83,51.91 107.83,51.28 107.96,51.15 108.15,51.15 108.28,51.28 108.28,51.62 108.6,51.93 112.49,51.93 arc(112.59,51.98) 112.63,52.08 arc(112.68,52.18) 112.78,52.22 112.94,52.22 arc(113.04,52.18) 113.09,52.08 arc(113.13,51.98) 113.23,51.93 113.59,51.93 v1(113.87,52.21)
MIPI_DSI_TX1_D1P: length 94.2
  TOP w0.124: v1(51.38,46.92) 51.68,47.21 52.32,47.21 52.68,47.57 52.68,52.79 52.76,52.88 J30.112 ; J19.20 129.14,51.53 129.06,51.61 114.19,51.61 v1(113.87,51.29)
  ART03 w0.113: v1(113.87,51.29) 113.54,51.62 108.73,51.62 108.59,51.49 108.59,51.15 108.28,50.83 107.83,50.83 107.51,51.15 107.51,51.78 107.4,51.9 107.22,51.9 107.06,51.74 107.06,51.15 106.74,50.83 106.29,50.83 105.98,51.15 105.98,51.66 105.85,51.79 105.66,51.79 105.53,51.66 105.53,51.15 105.21,50.83 87.64,50.83 86.78,49.98 69.99,49.98 67.14,47.13 61.03,47.13 59.3,48.86 52.8,48.86 52.56,48.63 52.56,47.52 52.12,47.07 51.54,47.07 v1(51.38,46.92)
MIPI_DSI_TX1_D2N: length 92.2
  TOP w0.124: J19.18 129.14,50.53 129.06,50.44 112.24,50.44 v1(111.97,50.71) ; J30.108 53.76,52.88 53.68,52.79 53.68,51.12 arc(53.72,51.01) 53.83,50.97 arc(53.93,50.93) 53.98,50.82 53.98,50.62 arc(53.93,50.52) 53.83,50.47 arc(53.72,50.43) 53.68,50.32 53.68,50.13 arc(53.72,50.02) 53.83,49.98 arc(53.93,49.93) 53.98,49.83 53.98,49.63 arc(53.93,49.53) 53.83,49.48 arc(53.72,49.44) 53.68,49.33 53.68,49.14 arc(53.72,49.03) 53.83,48.99 arc(53.93,48.94) 53.98,48.84 53.98,48.64 arc(53.93,48.53) 53.83,48.49 arc(53.72,48.45) 53.68,48.34 53.68,48.14 arc(53.72,48.04) 53.83,47.99 arc(53.93,47.95) 53.98,47.84 53.98,47.65 arc(53.93,47.54) 53.83,47.5 arc(53.72,47.45) 53.68,47.35 53.68,46.33 53.31,45.97 53.31,44.41 53.44,44.29 53.76,44.29 v1(54.05,44.58)
  ART03 w0.113: v1(111.97,50.71) 111.69,50.43 111.45,50.43 arc(111.36,50.47) 111.32,50.57 arc(111.28,50.66) 111.19,50.7 111,50.7 arc(110.91,50.66) 110.87,50.57 arc(110.83,50.47) 110.73,50.43 110.55,50.43 arc(110.45,50.47) 110.42,50.57 arc(110.38,50.66) 110.28,50.7 110.1,50.7 arc(110,50.66) 109.96,50.57 arc(109.93,50.47) 109.83,50.43 109.65,50.43 arc(109.55,50.47) 109.51,50.57 arc(109.47,50.66) 109.38,50.7 109.19,50.7 arc(109.1,50.66) 109.06,50.57 arc(109.02,50.47) 108.93,50.43 88.13,50.43 87.2,49.5 70.16,49.5 66.86,46.2 58.93,46.2 58.11,45.37 57.63,45.37 56.41,44.16 54.17,44.16 54.05,44.27 v1(54.05,44.58)
MIPI_DSI_TX1_D2P: length 90.2
  TOP w0.124: v1(111.97,49.79) 112.3,50.11 129.06,50.11 129.14,50.03 J19.17 ; v1(54.05,43.67) 53.76,43.96 53.3,43.96 52.99,44.28 52.99,46.11 53.35,46.47 53.35,52.79 53.26,52.88 J30.110
  ART03 w0.113: v1(54.05,43.67) 54.22,43.84 56.54,43.84 57.76,45.06 58.24,45.06 59.06,45.88 66.99,45.88 70.3,49.19 87.33,49.19 88.26,50.12 111.64,50.12 v1(111.97,49.79)
MIPI_DSI_TX1_D3N: length 94.7
  TOP w0.124: v1(115.83,56.74) 115.87,56.74 116.18,56.44 129.06,56.44 129.14,56.53 J19.30
  TOP w0.156: J30.104 54.76,52.08 v1(54.26,51.58)
  ART03 w0.113: v1(115.83,56.74) 115.52,56.43 112.91,56.43 112.59,56.12 112.59,55.78 112.46,55.65 112.27,55.65 112.14,55.78 112.14,56.52 111.82,56.84 111.37,56.84 111.06,56.52 111.06,55.78 110.92,55.65 110.74,55.65 110.6,55.78 110.6,56.32 110.29,56.64 109.84,56.64 109.52,56.32 109.52,55.78 109.39,55.65 109.2,55.65 109.07,55.78 109.07,56.12 108.75,56.43 108.3,56.43 107.99,56.12 107.99,55.78 107.86,55.65 107.67,55.65 107.54,55.78 107.54,56.12 107.22,56.43 106.77,56.43 106.45,56.12 106.45,55.78 106.32,55.65 106.13,55.65 106,55.78 106,56.12 105.69,56.43 105.24,56.43 104.92,56.12 104.92,55.78 104.79,55.65 104.6,55.65 104.47,55.78 104.47,56.12 104.15,56.43 103.7,56.43 103.39,56.12 103.39,55.78 103.25,55.65 103.07,55.65 102.93,55.78 102.93,56.12 102.62,56.43 102.17,56.43 101.85,56.12 101.85,55.78 101.72,55.65 101.53,55.65 101.4,55.78 101.4,56.12 101.08,56.43 100.63,56.43 100.32,56.12 100.32,55.78 100.18,55.65 100,55.65 99.87,55.78 99.87,56.12 99.55,56.43 99.1,56.43 98.78,56.12 98.78,55.78 98.65,55.65 98.46,55.65 98.33,55.78 98.33,56.12 98.01,56.43 89.5,56.43 88.9,57.03 84.86,57.03 81.98,54.16 54.35,54.16 53.8,53.61 53.8,52.39 54.26,51.93 v1(54.26,51.58)
MIPI_DSI_TX1_D3P: length 95.3
  TOP w0.124: J19.29 129.14,56.03 129.06,56.11 128.51,56.11 arc(128.43,56.08) 128.4,56 arc(128.37,55.92) 128.29,55.89 128.01,55.89 arc(127.93,55.92) 127.9,56 arc(127.87,56.08) 127.79,56.11 127.52,56.11 arc(127.44,56.08) 127.41,56 arc(127.37,55.92) 127.3,55.89 127.02,55.89 arc(126.94,55.92) 126.91,56 arc(126.88,56.08) 126.8,56.11 126.52,56.11 arc(126.45,56.08) 126.41,56 arc(126.38,55.92) 126.3,55.89 126.03,55.89 arc(125.95,55.92) 125.92,56 arc(125.89,56.08) 125.81,56.11 116.17,56.11 115.87,55.81 v1(115.83,55.81)
  TOP w0.156: J30.106 v1(54.26,52.58)
  ART03 w0.113: v1(54.26,52.58) 54.12,52.73 54.12,53.48 54.48,53.84 54.72,53.84 arc(54.81,53.8) 54.85,53.7 arc(54.9,53.61) 54.99,53.57 55.17,53.57 arc(55.27,53.61) 55.31,53.7 arc(55.35,53.8) 55.44,53.84 82.11,53.84 84.99,56.72 88.77,56.72 89.37,56.12 89.76,56.12 arc(89.85,56.08) 89.89,55.99 arc(89.93,55.89) 90.02,55.85 90.21,55.85 arc(90.3,55.89) 90.34,55.99 arc(90.38,56.08) 90.47,56.12 90.66,56.12 arc(90.75,56.08) 90.79,55.99 arc(90.83,55.89) 90.92,55.85 91.11,55.85 arc(91.2,55.89) 91.24,55.99 arc(91.28,56.08) 91.37,56.12 91.56,56.12 arc(91.66,56.08) 91.69,55.99 arc(91.73,55.89) 91.83,55.85 92.01,55.85 arc(92.11,55.89) 92.15,55.99 arc(92.18,56.08) 92.28,56.12 92.46,56.12 arc(92.56,56.08) 92.6,55.99 arc(92.64,55.89) 92.73,55.85 92.92,55.85 arc(93.01,55.89) 93.05,55.99 arc(93.09,56.08) 93.18,56.12 93.37,56.12 arc(93.46,56.08) 93.5,55.99 arc(93.54,55.89) 93.63,55.85 93.82,55.85 arc(93.91,55.89) 93.95,55.99 arc(93.99,56.08) 94.08,56.12 94.27,56.12 arc(94.36,56.08) 94.4,55.99 arc(94.44,55.89) 94.53,55.85 94.72,55.85 arc(94.81,55.89) 94.85,55.99 arc(94.89,56.08) 94.98,56.12 95.17,56.12 arc(95.26,56.08) 95.3,55.99 arc(95.34,55.89) 95.43,55.85 95.62,55.85 arc(95.72,55.89) 95.75,55.99 arc(95.79,56.08) 95.89,56.12 96.07,56.12 arc(96.17,56.08) 96.21,55.99 arc(96.24,55.89) 96.34,55.85 96.52,55.85 arc(96.62,55.89) 96.66,55.99 arc(96.7,56.08) 96.79,56.12 97.88,56.12 98.02,55.99 98.02,55.65 98.33,55.33 98.78,55.33 99.1,55.65 99.1,55.99 99.23,56.12 99.42,56.12 99.55,55.99 99.55,55.65 99.87,55.33 100.32,55.33 100.63,55.65 100.63,55.99 100.76,56.12 100.95,56.12 101.08,55.99 101.08,55.65 101.4,55.33 101.85,55.33 102.17,55.65 102.17,55.99 102.3,56.12 102.49,56.12 102.62,55.99 102.62,55.65 102.94,55.33 103.38,55.33 103.7,55.65 103.7,55.99 103.83,56.12 104.02,56.12 104.15,55.99 104.15,55.65 104.47,55.33 104.92,55.33 105.24,55.65 105.24,55.99 105.37,56.12 105.55,56.12 105.69,55.99 105.69,55.65 106,55.33 106.45,55.33 106.77,55.65 106.77,55.99 106.9,56.12 107.09,56.12 107.22,55.99 107.22,55.65 107.54,55.33 107.99,55.33 108.3,55.65 108.3,55.99 108.44,56.12 108.62,56.12 108.75,55.99 108.75,55.65 109.07,55.33 109.52,55.33 109.84,55.65 109.84,56.19 109.97,56.32 110.16,56.32 110.29,56.19 110.29,55.65 110.61,55.33 111.05,55.33 111.37,55.65 111.37,56.39 111.5,56.52 111.69,56.52 111.82,56.39 111.82,55.65 112.14,55.33 112.59,55.33 112.91,55.65 112.91,55.99 113.04,56.12 115.53,56.12 v1(115.83,55.81)
OTG0_DM: length 8.3
  TOP w0.158: v1(28.31,85.47) 28.01,85.17 28.01,84.34 28.08,84.27 J16.B7 28.08,81.69 27.89,81.51 27.26,81.51 27.08,81.69 J16.A7
  BOTTOM w0.158: v1(28.31,85.47) 28.31,86.09 D33.2 28.46,87.22 R134.1
OTG0_DP: length 7
  TOP w0.158: 27.58,84.27 27.65,84.34 27.65,85.17 v1(27.35,85.47) ; 27.58,84.27 27.36,84.27 27.05,84.58 26.8,84.58 26.58,84.36 J16.B6 ; 27.58,84.27 J16.A6
  BOTTOM w0.158: v1(27.35,85.47) 27.42,85.55 D34.2 27.41,86.25 R135.1
PCIE20_CLKREQN_M0: length 115.8
  TOP w0.156: v1(34.01,64.75) 34.51,64.25 J30.177
  ART03 w0.142: v1(34.01,64.75) 34.53,65.28 35.28,65.28 36.93,66.93 41.53,66.93 44.96,70.36 49.91,70.36 51.31,71.75 51.31,77.16 52.2,78.05 52.2,86.99 53.85,88.64 86.92,88.64 v1(87.17,88.39)
  ART04 w0.142: v1(87.17,88.39) 87.66,87.91 87.66,86.77 89.18,85.24 102.67,85.24 103.35,84.56 103.35,74.01 104.17,73.2 113.37,73.2 v1(113.8,72.77)
  BOTTOM w0.156: R210.1 113.6,72.57 v1(113.8,72.77)
PCIE20_PERSTN_M0: length 120.5
  TOP w0.156: R212.2 v1(104.27,57.44) ; J30.175 v1(35.01,63.75)
  ART03 w0.142: v1(35.01,63.75) 37.17,65.91 41.91,65.91 45.42,69.42 50.62,69.42 52.32,71.12 52.32,76.58 53.47,77.72 53.47,86.5 54.85,87.88 86,87.88 86.5,87.39 v1(87.17,87.39)
  ART04 w0.142: v1(104.27,57.44) 104.84,56.87 105.62,56.87 105.87,57.11 105.87,57.78 105.16,58.5 105.16,71.42 102.84,73.74 102.84,83.74 101.83,84.76 88.87,84.76 87.17,86.46 v1(87.17,87.39)
PCIE20_REFCLKN: length 94.4
  TOP w0.179: v1(91.39,61.57) 91.08,61.87 91.08,64.46 91.26,64.64 104.83,64.64 105.56,65.37 105.56,67.84 106.1,68.38 111.34,68.38 111.79,68.83 111.79,69.89 112,70.1 J24.11 ; v1(86.74,61.24) 86.44,60.93 84.91,60.93 83.79,59.82 80.99,59.82 79.09,57.91 69.78,57.91 68.66,59.03 33.63,59.03 33.45,59.21 33.45,60.93 33.51,60.98 J30.181
  BOTTOM w0.179: v1(91.39,61.57) 91.08,61.87 91.08,62.59 90.68,62.99 89.61,62.99 87.55,60.93 87.04,60.93 v1(86.74,61.24)
PCIE20_REFCLKP: length 94.4
  TOP w0.179: J30.183 33.01,60.98 33.07,60.93 33.07,59.05 33.47,58.65 68.5,58.65 69.62,57.53 79.25,57.53 81.15,59.43 83.95,59.43 85.06,60.55 86.44,60.55 v1(86.74,60.25) ; v1(90.4,61.57) 90.7,61.87 90.7,64.62 91.1,65.02 104.67,65.02 105.18,65.53 105.18,68 105.94,68.76 111.18,68.76 111.41,68.99 111.41,69.89 111.2,70.1 J24.13
  BOTTOM w0.179: v1(90.4,61.57) 90.7,61.87 90.7,62.43 90.52,62.61 89.76,62.61 87.71,60.55 87.04,60.55 v1(86.74,60.25)
